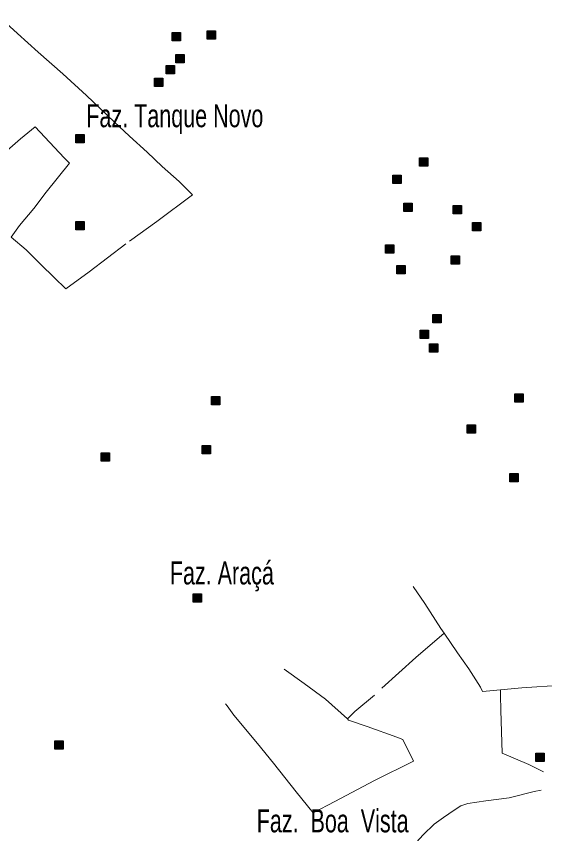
# Model space of a CAD drawing. Extents: x 445.6 to 500, y 8618.1 to 8673.4.
# Drawn here: x 456.65 to 460.33, y 8634.54 to 8640.23 of the extents above; entities that cross this region are included whole.
import ezdxf

# ---------------------------------------------------------------- set-up
doc = ezdxf.new("R2010")
doc.units = 0
doc.header["$LTSCALE"] = 0.064
doc.linetypes.add('DOT_DASHED', pattern=[7.7, 5, -1.2, 0.3, -1.2])
doc.layers.add('2', color=7, linetype='Continuous', lineweight=25)
doc.layers.add('22', color=7, linetype='DOT_DASHED', lineweight=13)
doc.layers.add('61', color=7, linetype='Continuous')

msp = doc.modelspace()

# ---------------------------------------------------------------- hatches: boundary and pattern name
at = {"layer": '2'}
for points in [[(457.7381, 8640.1145), (457.7961, 8640.1145), (457.7961, 8640.0565), (457.7381, 8640.0565)], [(457.9821, 8640.1252), (458.0401, 8640.1252), (458.0401, 8640.0672), (457.9821, 8640.0672)], [(457.763, 8639.9621), (457.821, 8639.9621), (457.821, 8639.9041), (457.763, 8639.9041)], [(457.6954, 8639.8841), (457.7534, 8639.8841), (457.7534, 8639.8261), (457.6954, 8639.8261)], [(457.6144, 8639.7961), (457.6724, 8639.7961), (457.6724, 8639.7381), (457.6144, 8639.7381)], [(457.0672, 8639.4031), (457.1252, 8639.4031), (457.1252, 8639.3451), (457.0672, 8639.3451)], [(459.4601, 8639.2405), (459.5181, 8639.2405), (459.5181, 8639.1825), (459.4601, 8639.1825)], [(459.2743, 8639.1219), (459.3323, 8639.1219), (459.3323, 8639.0639), (459.2743, 8639.0639)], [(459.3509, 8638.9257), (459.4089, 8638.9257), (459.4089, 8638.8677), (459.3509, 8638.8677)], [(459.6945, 8638.909), (459.7525, 8638.909), (459.7525, 8638.851), (459.6945, 8638.851)], [(457.0678, 8638.799), (457.1258, 8638.799), (457.1258, 8638.741), (457.0678, 8638.741)], [(459.8275, 8638.7923), (459.8855, 8638.7923), (459.8855, 8638.7343), (459.8275, 8638.7343)], [(459.2235, 8638.6367), (459.2815, 8638.6367), (459.2815, 8638.5787), (459.2235, 8638.5787)], [(459.6796, 8638.5582), (459.7376, 8638.5582), (459.7376, 8638.5002), (459.6796, 8638.5002)], [(459.3011, 8638.4922), (459.3591, 8638.4922), (459.3591, 8638.4342), (459.3011, 8638.4342)], [(459.5511, 8638.1512), (459.6091, 8638.1512), (459.6091, 8638.0932), (459.5511, 8638.0932)], [(459.463, 8638.042), (459.521, 8638.042), (459.521, 8637.984), (459.463, 8637.984)], [(459.5295, 8637.9475), (459.5875, 8637.9475), (459.5875, 8637.8895), (459.5295, 8637.8895)], [(458.0103, 8637.5791), (458.0683, 8637.5791), (458.0683, 8637.5211), (458.0103, 8637.5211)], [(460.1237, 8637.598), (460.1817, 8637.598), (460.1817, 8637.54), (460.1237, 8637.54)], [(459.7899, 8637.3819), (459.8479, 8637.3819), (459.8479, 8637.3239), (459.7899, 8637.3239)], [(457.9473, 8637.2383), (458.0053, 8637.2383), (458.0053, 8637.1803), (457.9473, 8637.1803)], [(457.2429, 8637.1871), (457.3009, 8637.1871), (457.3009, 8637.1291), (457.2429, 8637.1291)], [(460.0891, 8637.0428), (460.1471, 8637.0428), (460.1471, 8636.9848), (460.0891, 8636.9848)], [(457.8842, 8636.2064), (457.9422, 8636.2064), (457.9422, 8636.1484), (457.8842, 8636.1484)], [(456.9219, 8635.1828), (456.9799, 8635.1828), (456.9799, 8635.1248), (456.9219, 8635.1248)], [(460.2698, 8635.0964), (460.3278, 8635.0964), (460.3278, 8635.0384), (460.2698, 8635.0384)]]:
    msp.add_hatch(color=256, dxfattribs=at).paths.add_polyline_path(points)

# ---------------------------------------------------------------- linework, layer by layer
for points in [[(457.7381, 8640.1145), (457.7961, 8640.1145), (457.7961, 8640.0565), (457.7381, 8640.0565)], [(457.9821, 8640.1252), (458.0401, 8640.1252), (458.0401, 8640.0672), (457.9821, 8640.0672)], [(457.763, 8639.9621), (457.821, 8639.9621), (457.821, 8639.9041), (457.763, 8639.9041)], [(457.6954, 8639.8841), (457.7534, 8639.8841), (457.7534, 8639.8261), (457.6954, 8639.8261)], [(457.6144, 8639.7961), (457.6724, 8639.7961), (457.6724, 8639.7381), (457.6144, 8639.7381)], [(457.0672, 8639.4031), (457.1252, 8639.4031), (457.1252, 8639.3451), (457.0672, 8639.3451)], [(459.4601, 8639.2405), (459.5181, 8639.2405), (459.5181, 8639.1825), (459.4601, 8639.1825)], [(459.2743, 8639.1219), (459.3323, 8639.1219), (459.3323, 8639.0639), (459.2743, 8639.0639)], [(459.3509, 8638.9257), (459.4089, 8638.9257), (459.4089, 8638.8677), (459.3509, 8638.8677)], [(459.6945, 8638.909), (459.7525, 8638.909), (459.7525, 8638.851), (459.6945, 8638.851)], [(457.0678, 8638.799), (457.1258, 8638.799), (457.1258, 8638.741), (457.0678, 8638.741)], [(459.8275, 8638.7923), (459.8855, 8638.7923), (459.8855, 8638.7343), (459.8275, 8638.7343)], [(459.2235, 8638.6367), (459.2815, 8638.6367), (459.2815, 8638.5787), (459.2235, 8638.5787)], [(459.6796, 8638.5582), (459.7376, 8638.5582), (459.7376, 8638.5002), (459.6796, 8638.5002)], [(459.3011, 8638.4922), (459.3591, 8638.4922), (459.3591, 8638.4342), (459.3011, 8638.4342)], [(459.5511, 8638.1512), (459.6091, 8638.1512), (459.6091, 8638.0932), (459.5511, 8638.0932)], [(459.463, 8638.042), (459.521, 8638.042), (459.521, 8637.984), (459.463, 8637.984)], [(459.5295, 8637.9475), (459.5875, 8637.9475), (459.5875, 8637.8895), (459.5295, 8637.8895)], [(458.0103, 8637.5791), (458.0683, 8637.5791), (458.0683, 8637.5211), (458.0103, 8637.5211)], [(460.1237, 8637.598), (460.1817, 8637.598), (460.1817, 8637.54), (460.1237, 8637.54)], [(459.7899, 8637.3819), (459.8479, 8637.3819), (459.8479, 8637.3239), (459.7899, 8637.3239)], [(457.9473, 8637.2383), (458.0053, 8637.2383), (458.0053, 8637.1803), (457.9473, 8637.1803)], [(457.2429, 8637.1871), (457.3009, 8637.1871), (457.3009, 8637.1291), (457.2429, 8637.1291)], [(460.0891, 8637.0428), (460.1471, 8637.0428), (460.1471, 8636.9848), (460.0891, 8636.9848)], [(457.8842, 8636.2064), (457.9422, 8636.2064), (457.9422, 8636.1484), (457.8842, 8636.1484)], [(456.9219, 8635.1828), (456.9799, 8635.1828), (456.9799, 8635.1248), (456.9219, 8635.1248)], [(460.2698, 8635.0964), (460.3278, 8635.0964), (460.3278, 8635.0384), (460.2698, 8635.0384)]]:
    msp.add_lwpolyline(points, close=True, dxfattribs=at)
at = {"layer": '22'}
for points in [[(456.5312, 8639.2444), (456.6807, 8639.3736), (456.7833, 8639.4583), (456.9864, 8639.2421), (457.0221, 8639.2042), (456.8615, 8639.0036), (456.7744, 8638.8877), (456.6741, 8638.7705), (456.6161, 8638.6902), (456.721, 8638.6011), (456.8237, 8638.4986), (456.9152, 8638.4094), (456.9977, 8638.3292), (457.1607, 8638.4473), (457.4396, 8638.6613), (457.6315, 8638.7972), (457.8802, 8638.9847), (457.7865, 8639.0761), (457.6682, 8639.1809), (457.5633, 8639.2812), (457.4405, 8639.392), (457.3333, 8639.4923), (457.1414, 8639.6751), (456.9763, 8639.8266), (456.8036, 8639.9771), (456.6608, 8640.1064), (456.5291, 8640.2268)], [(459.4159, 8636.2573), (459.4972, 8636.1392), (459.6074, 8635.9636), (459.6301, 8635.9307)], [(459.6301, 8635.9307), (459.4343, 8635.7619), (459.145, 8635.5012), (459.0085, 8635.3859), (458.9569, 8635.3343)], [(459.6301, 8635.9307), (459.7229, 8635.7959), (459.8016, 8635.6833), (459.8829, 8635.5548), (459.8987, 8635.526), (460.0234, 8635.538)], [(458.5172, 8635.6808), (458.6562, 8635.5818), (458.8042, 8635.4716), (458.9569, 8635.3343)], [(460.0234, 8635.538), (460.1715, 8635.5522), (460.4523, 8635.5706), (460.6464, 8635.5889), (460.6993, 8635.5912)], [(460.3212, 8634.9664), (460.2202, 8635.0183), (460.0337, 8635.0965), (460.0262, 8635.3947), (460.0235, 8635.4973), (460.0234, 8635.538)], [(458.9569, 8635.3343), (458.9656, 8635.3265), (459.0947, 8635.2809), (459.3018, 8635.2083), (459.343, 8635.1915), (459.4183, 8635.041), (459.1466, 8634.9067), (458.8695, 8634.7589), (458.7182, 8634.6799), (458.5998, 8634.8277), (458.4438, 8635.0265), (458.3308, 8635.1635), (458.1667, 8635.361), (458.1209, 8635.4255), (458.1098, 8635.44)], [(459.4386, 8634.4768), (459.4843, 8634.5279), (459.5609, 8634.6027), (459.6257, 8634.6485), (459.7014, 8634.6998), (459.7473, 8634.7295), (459.7959, 8634.7457), (459.9202, 8634.7646), (460.0824, 8634.7862), (460.258, 8634.8294), (460.3052, 8634.8379)]]:
    msp.add_lwpolyline(points, dxfattribs=at)

# ---------------------------------------------------------------- texts
at = {"layer": '61', "width": 0.7}
for s, p in [('Faz. Tanque Novo', (457.1401, 8639.4548)), ('Faz. Araçá', (457.7214, 8636.2712)), ('Faz.  Boa  Vista', (458.3262, 8634.5449))]:
    msp.add_text(s, height=0.16, dxfattribs=at).set_placement(p)

doc.saveas('drawing.dxf')
